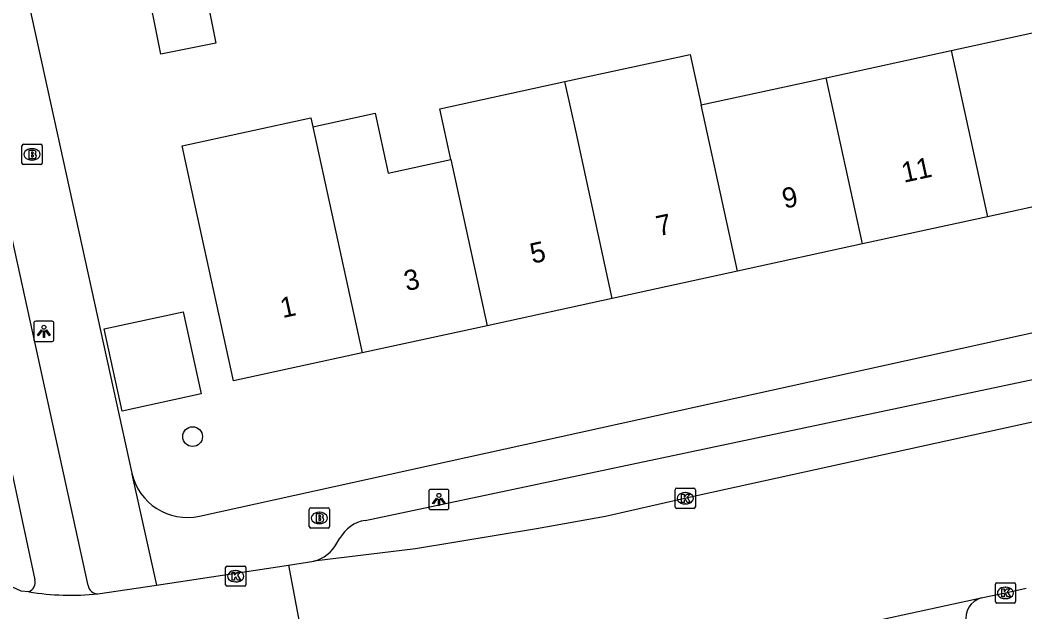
# Model space of a CAD drawing. Extents: x 160557 to 161245, y 385330 to 386505.
# Drawn here: x 160730.97 to 160780.64, y 385909.32 to 385938.59 of the extents above; entities that cross this region are included whole.
import ezdxf

# ---------------------------------------------------------------- set-up
doc = ezdxf.new("R2010")
doc.units = 0
for name, color, linetype in [('IMGEO_Boom', 7, 'Continuous'), ('IMGEO_Brandkraan', 7, 'Continuous'), ('IMGEO_Fietspad_gesloten', 7, 'Continuous'), ('IMGEO_Kolk', 7, 'Continuous'), ('IMGEO_Lichtpunt', 7, 'Continuous'), ('IMGEO_Pand', 7, 'Continuous'), ('IMGEO_Pand_nummerreeks', 7, 'Continuous'), ('IMGEO_Rijbaan_lokaal_gesloten', 7, 'Continuous'), ('IMGEO_Voetpad_open', 7, 'Continuous')]:
    doc.layers.add(name, color=color, linetype=linetype)

msp = doc.modelspace()

# ---------------------------------------------------------------- linework, layer by layer
at = {"layer": 'IMGEO_Boom'}
msp.add_circle((160739.497, 385917.986), 0.489, dxfattribs=at)
at = {"layer": 'IMGEO_Brandkraan'}
for p, q in [((160731.062, 385931.519), (160731.062, 385932.371)), ((160731.137, 385932.445), (160731.989, 385932.445)), ((160732.063, 385932.371), (160732.063, 385931.519)), ((160731.55, 385932.225), (160731.575, 385932.225)), ((160731.989, 385931.445), (160731.137, 385931.445)), ((160731.573, 385931.665), (160731.548, 385931.665)), ((160745.34, 385914.462), (160746.192, 385914.462)), ((160745.265, 385913.536), (160745.265, 385914.388)), ((160745.753, 385914.242), (160745.778, 385914.242)), ((160746.266, 385914.388), (160746.266, 385913.536)), ((160746.192, 385913.462), (160745.34, 385913.462)), ((160745.776, 385913.682), (160745.751, 385913.682))]:
    msp.add_line(p, q, dxfattribs=at)
for points in [[(160731.062, 385931.519), (160731.062, 385932.371)], [(160731.137, 385932.445), (160731.989, 385932.445)], [(160732.063, 385932.371), (160732.063, 385931.519)], [(160731.41, 385932.145), (160731.41, 385931.745), (160731.623, 385931.745)], [(160731.641, 385932.145), (160731.41, 385932.145)], [(160731.589, 385932.064), (160731.535, 385932.064), (160731.535, 385931.988)], [(160731.535, 385931.988), (160731.588, 385931.988)], [(160731.597, 385931.912), (160731.535, 385931.912), (160731.535, 385931.831)], [(160731.535, 385931.831), (160731.597, 385931.831)], [(160731.989, 385931.445), (160731.137, 385931.445)], [(160745.34, 385914.462), (160746.192, 385914.462)], [(160745.265, 385913.536), (160745.265, 385914.388)], [(160745.613, 385914.162), (160745.613, 385913.762), (160745.826, 385913.762)], [(160745.844, 385914.162), (160745.613, 385914.162)], [(160745.792, 385914.081), (160745.738, 385914.081), (160745.738, 385914.005)], [(160745.738, 385914.005), (160745.791, 385914.005)], [(160746.266, 385914.388), (160746.266, 385913.536)], [(160746.192, 385913.462), (160745.34, 385913.462)], [(160745.8, 385913.929), (160745.738, 385913.929), (160745.738, 385913.848)], [(160745.738, 385913.848), (160745.8, 385913.848)]]:
    msp.add_lwpolyline(points, dxfattribs=at)
for centre, radius, start, end in [((160731.139, 385932.369), 0.0765, 91.552, 178.448), ((160731.139, 385932.369), 0.0765, 91.552, 178.448), ((160731.987, 385932.369), 0.0765, 1.552, 88.448), ((160731.987, 385932.369), 0.0765, 1.552, 88.448), ((160731.59, 385932.026), 0.0379, 267.8285, 90.9355), ((160731.598, 385931.871), 0.0404, 269.8759, 90.5077), ((160731.645, 385932), 0.145, 59.4692, 91.5367), ((160731.67, 385932.047), 0.0922, 285.5137, 58.1501), ((160731.675, 385931.855), 0.105, 301.3115, 78.989), ((160731.139, 385931.521), 0.0765, 181.552, 268.448), ((160731.139, 385931.521), 0.0765, 181.552, 268.448), ((160731.629, 385931.996), 0.251, 268.6676, 293.5347), ((160731.987, 385931.521), 0.0765, 271.552, 358.448), ((160731.987, 385931.521), 0.0765, 271.552, 358.448), ((160745.342, 385914.386), 0.0765, 91.552, 178.448), ((160745.342, 385914.386), 0.0765, 91.552, 178.448), ((160746.19, 385914.386), 0.0765, 1.552, 88.448), ((160746.19, 385914.386), 0.0765, 1.552, 88.448), ((160745.793, 385914.043), 0.0379, 267.8285, 90.9355), ((160745.848, 385914.017), 0.145, 59.4692, 91.5367), ((160745.873, 385914.064), 0.0922, 285.5137, 58.1501), ((160745.878, 385913.872), 0.105, 301.3115, 78.989), ((160745.342, 385913.538), 0.0765, 181.552, 268.448), ((160745.342, 385913.538), 0.0765, 181.552, 268.448), ((160745.801, 385913.888), 0.0404, 269.8759, 90.5077), ((160745.832, 385914.013), 0.251, 268.6676, 293.5347), ((160746.19, 385913.538), 0.0765, 271.552, 358.448), ((160746.19, 385913.538), 0.0765, 271.552, 358.448)]:
    msp.add_arc(centre, radius, start, end, dxfattribs=at)
for centre, major_axis, ratio, start_param, end_param in [((160731.549, 385931.945), (-0.387, 0.002), 0.722429, 4.712389, 7.853982), ((160731.574, 385931.945), (-0.39, 0.002), 0.717154, 1.570796, 4.712389), ((160745.752, 385913.962), (-0.387, 0.002), 0.722429, 4.712389, 7.853982), ((160745.777, 385913.962), (-0.39, 0.002), 0.717154, 1.570796, 4.712389)]:
    msp.add_ellipse(centre, major_axis=major_axis, ratio=ratio, start_param=start_param, end_param=end_param, dxfattribs=at)
at = {"layer": 'IMGEO_Fietspad_gesloten'}
for points in [[(160734.335, 385910.619), (160688.379, 386120.515), (160685.475, 386134.246), (160684.879, 386136.929)], [(160730.198, 385917.932), (160731.706, 385910.91)]]:
    msp.add_lwpolyline(points, dxfattribs=at)
for centre, radius, start, end in [((160731.206, 385910.787), 0.515, 292.3979, 13.7854), ((160734.82, 385910.698), 0.492, 189.2151, 270.0695)]:
    msp.add_arc(centre, radius, start, end, dxfattribs=at)
at = {"layer": 'IMGEO_Kolk'}
for p, q in [((160763.425, 385915.435), (160764.277, 385915.435)), ((160763.35, 385914.509), (160763.35, 385915.361)), ((160763.838, 385915.215), (160763.863, 385915.215)), ((160764.351, 385915.361), (160764.351, 385914.509)), ((160764.277, 385914.435), (160763.425, 385914.435)), ((160763.861, 385914.655), (160763.836, 385914.655)), ((160741.129, 385910.656), (160741.129, 385911.508)), ((160741.204, 385911.582), (160742.056, 385911.582)), ((160742.13, 385911.508), (160742.13, 385910.656)), ((160741.617, 385911.362), (160741.642, 385911.362)), ((160742.056, 385910.582), (160741.204, 385910.582)), ((160741.64, 385910.802), (160741.615, 385910.802)), ((160779.176, 385909.83), (160779.176, 385910.682)), ((160779.251, 385910.756), (160780.103, 385910.756)), ((160779.664, 385910.536), (160779.689, 385910.536)), ((160780.177, 385910.682), (160780.177, 385909.83)), ((160779.687, 385909.976), (160779.662, 385909.976)), ((160780.103, 385909.756), (160779.251, 385909.756))]:
    msp.add_line(p, q, dxfattribs=at)
for points in [[(160763.425, 385915.435), (160764.277, 385915.435)], [(160763.35, 385914.509), (160763.35, 385915.361)], [(160763.671, 385915.135), (160763.794, 385915.135), (160763.794, 385914.984), (160763.924, 385915.135), (160764.088, 385915.135), (160763.942, 385914.984), (160764.095, 385914.735), (160763.943, 385914.735), (160763.858, 385914.899), (160763.794, 385914.832), (160763.794, 385914.735), (160763.671, 385914.735), (160763.671, 385915.135)], [(160764.351, 385915.361), (160764.351, 385914.509)], [(160764.277, 385914.435), (160763.425, 385914.435)], [(160741.129, 385910.656), (160741.129, 385911.508)], [(160741.204, 385911.582), (160742.056, 385911.582)], [(160742.13, 385911.508), (160742.13, 385910.656)], [(160741.45, 385911.282), (160741.573, 385911.282), (160741.573, 385911.131), (160741.703, 385911.282), (160741.867, 385911.282), (160741.721, 385911.131), (160741.874, 385910.882), (160741.722, 385910.882), (160741.637, 385911.046), (160741.573, 385910.979), (160741.573, 385910.882), (160741.45, 385910.882), (160741.45, 385911.282)], [(160742.056, 385910.582), (160741.204, 385910.582)], [(160779.176, 385909.83), (160779.176, 385910.682)], [(160779.251, 385910.756), (160780.103, 385910.756)], [(160780.177, 385910.682), (160780.177, 385909.83)], [(160779.497, 385910.456), (160779.62, 385910.456), (160779.62, 385910.305), (160779.75, 385910.456), (160779.914, 385910.456), (160779.768, 385910.305), (160779.921, 385910.056), (160779.769, 385910.056), (160779.684, 385910.22), (160779.62, 385910.153), (160779.62, 385910.056), (160779.497, 385910.056), (160779.497, 385910.456)], [(160780.103, 385909.756), (160779.251, 385909.756)]]:
    msp.add_lwpolyline(points, dxfattribs=at)
for centre, start, end in [((160763.427, 385915.359), 91.552, 178.448), ((160763.427, 385915.359), 91.552, 178.448), ((160764.275, 385915.359), 1.552, 88.448), ((160764.275, 385915.359), 1.552, 88.448), ((160763.427, 385914.511), 181.552, 268.448), ((160763.427, 385914.511), 181.552, 268.448), ((160764.275, 385914.511), 271.552, 358.448), ((160764.275, 385914.511), 271.552, 358.448), ((160741.206, 385911.506), 91.552, 178.448), ((160741.206, 385911.506), 91.552, 178.448), ((160742.054, 385911.506), 1.552, 88.448), ((160742.054, 385911.506), 1.552, 88.448), ((160741.206, 385910.658), 181.552, 268.448), ((160741.206, 385910.658), 181.552, 268.448), ((160742.054, 385910.658), 271.552, 358.448), ((160742.054, 385910.658), 271.552, 358.448), ((160779.253, 385910.68), 91.552, 178.448), ((160779.253, 385910.68), 91.552, 178.448), ((160780.101, 385910.68), 1.552, 88.448), ((160780.101, 385910.68), 1.552, 88.448), ((160779.253, 385909.832), 181.552, 268.448), ((160779.253, 385909.832), 181.552, 268.448), ((160780.101, 385909.832), 271.552, 358.448), ((160780.101, 385909.832), 271.552, 358.448)]:
    msp.add_arc(centre, 0.0765, start, end, dxfattribs=at)
for centre, major_axis, ratio, start_param, end_param in [((160763.837, 385914.935), (-0.387, 0.002), 0.722429, 4.712389, 7.853982), ((160763.862, 385914.935), (-0.39, 0.002), 0.717154, 1.570796, 4.712389), ((160741.616, 385911.082), (-0.387, 0.002), 0.722429, 4.712389, 7.853982), ((160741.641, 385911.082), (-0.39, 0.002), 0.717154, 1.570796, 4.712389), ((160779.663, 385910.256), (-0.387, 0.002), 0.722429, 4.712389, 7.853982), ((160779.688, 385910.256), (-0.39, 0.002), 0.717154, 1.570796, 4.712389)]:
    msp.add_ellipse(centre, major_axis=major_axis, ratio=ratio, start_param=start_param, end_param=end_param, dxfattribs=at)
at = {"layer": 'IMGEO_Lichtpunt'}
for p, q in [((160731.648, 385923.6), (160731.648, 385922.793)), ((160731.648, 385923.6), (160731.648, 385922.793)), ((160732.55, 385923.695), (160731.742, 385923.695)), ((160732.55, 385923.695), (160731.742, 385923.695)), ((160732.644, 385922.793), (160732.644, 385923.6)), ((160732.644, 385922.793), (160732.644, 385923.6)), ((160731.742, 385922.699), (160732.55, 385922.699)), ((160731.742, 385922.699), (160732.55, 385922.699)), ((160751.173, 385915.283), (160751.173, 385914.476)), ((160751.173, 385915.283), (160751.173, 385914.476)), ((160752.075, 385915.378), (160751.267, 385915.378)), ((160752.075, 385915.378), (160751.267, 385915.378)), ((160752.169, 385914.476), (160752.169, 385915.283)), ((160752.169, 385914.476), (160752.169, 385915.283)), ((160751.267, 385914.382), (160752.075, 385914.382)), ((160751.267, 385914.382), (160752.075, 385914.382))]:
    msp.add_line(p, q, dxfattribs=at)
for points in [[(160732.022, 385923.264), (160732.061, 385923.236), (160731.873, 385922.974), (160731.835, 385923.001), (160732.022, 385923.264)], [(160732.124, 385923.216), (160732.171, 385923.216), (160732.171, 385922.894), (160732.124, 385922.894), (160732.124, 385923.216)], [(160732.234, 385923.236), (160732.272, 385923.263), (160732.459, 385923.001), (160732.42, 385922.973), (160732.234, 385923.236)], [(160751.547, 385914.947), (160751.586, 385914.919), (160751.398, 385914.657), (160751.36, 385914.684), (160751.547, 385914.947)], [(160751.759, 385914.919), (160751.797, 385914.946), (160751.984, 385914.684), (160751.945, 385914.656), (160751.759, 385914.919)], [(160751.649, 385914.899), (160751.696, 385914.899), (160751.696, 385914.577), (160751.649, 385914.577), (160751.649, 385914.899)]]:
    msp.add_lwpolyline(points, dxfattribs=at)
for centre in [(160732.147, 385923.398), (160751.672, 385915.081)]:
    msp.add_circle(centre, 0.0994, dxfattribs=at)
for centre, start, end in [((160731.742, 385923.6), 90, 180), ((160731.742, 385923.6), 90, 180), ((160732.55, 385923.6), 0, 90), ((160732.55, 385923.6), 0, 90), ((160731.742, 385922.793), 180, 270), ((160731.742, 385922.793), 180, 270), ((160732.55, 385922.793), 270, 0), ((160732.55, 385922.793), 270, 360), ((160751.267, 385915.283), 90, 180), ((160751.267, 385915.283), 90, 180), ((160752.075, 385915.283), 0, 90), ((160752.075, 385915.283), 0, 90), ((160751.267, 385914.476), 180, 270), ((160751.267, 385914.476), 180, 270), ((160752.075, 385914.476), 270, 0), ((160752.075, 385914.476), 270, 360)]:
    msp.add_arc(centre, 0.0946, start, end, dxfattribs=at)
at = {"layer": 'IMGEO_Pand'}
for points in [[(160739.868, 385941.328), (160740.651, 385937.453), (160737.93, 385936.903), (160737.146, 385940.778)], [(160776.999, 385937.087), (160783.35, 385938.471), (160783.85, 385936.177), (160784.078, 385935.132), (160785.143, 385930.246), (160778.791, 385928.861)], [(160757.905, 385935.545), (160764.087, 385936.892), (160764.632, 385934.391)], [(160770.816, 385935.739), (160776.999, 385937.087)], [(160776.999, 385937.087), (160778.791, 385928.861)], [(160752.267, 385931.695), (160751.722, 385934.198), (160757.905, 385935.545)], [(160760.243, 385924.818), (160758.45, 385933.043), (160757.905, 385935.545)], [(160764.632, 385934.391), (160770.816, 385935.739)], [(160772.608, 385927.514), (160770.816, 385935.739)], [(160766.424, 385926.166), (160764.632, 385934.391)], [(160745.439, 385933.314), (160748.515, 385933.984), (160749.161, 385931.018), (160752.267, 385931.695)], [(160747.877, 385922.123), (160741.525, 385920.738), (160739.732, 385928.963), (160738.991, 385932.365), (160745.342, 385933.75), (160745.439, 385933.314)], [(160745.439, 385933.314), (160747.877, 385922.123)], [(160752.267, 385931.695), (160754.059, 385923.47)], [(160778.791, 385928.861), (160772.608, 385927.514)], [(160772.608, 385927.514), (160766.424, 385926.166)], [(160766.424, 385926.166), (160760.243, 385924.818)], [(160760.243, 385924.818), (160754.059, 385923.47)], [(160739.03, 385924.166), (160739.917, 385920.096), (160736.015, 385919.246), (160735.128, 385923.315), (160739.03, 385924.166)], [(160754.059, 385923.47), (160747.877, 385922.123)]]:
    msp.add_lwpolyline(points, dxfattribs=at)
at = {"layer": 'IMGEO_Rijbaan_lokaal_gesloten'}
for points in [[(160840.924, 385932.085), (160816.018, 385926.352), (160787.915, 385920.21), (160763.809, 385914.925), (160759.912, 385914.039), (160756.492, 385913.428), (160750.518, 385912.437), (160745.49, 385911.828)], [(160737.71, 385910.645), (160744.233, 385911.636)], [(160744.233, 385911.636), (160745.49, 385911.828)], [(160744.233, 385911.636), (160746.075, 385901.918)], [(160731.402, 385910.311), (160731.032, 385910.335), (160728.768, 385911.384)], [(160734.821, 385910.206), (160737.71, 385910.645)], [(160778.483, 385910.006), (160779.677, 385910.257), (160780.7, 385910.486)], [(160770.117, 385908.203), (160778.483, 385910.006)]]:
    msp.add_lwpolyline(points, dxfattribs=at)
msp.add_arc((160733.52, 385923.547), 13.405, 260.9107, 275.5713, dxfattribs=at)
at = {"layer": 'IMGEO_Voetpad_open'}
for points in [[(160731.429, 385939.532), (160731.466, 385939.363), (160731.404, 385939.381), (160736.496, 385916.182)], [(160739.836, 385914.053), (160789.869, 385925.075)], [(160748.031, 385913.844), (160786.716, 385922.012)], [(160736.496, 385916.182), (160736.503, 385916.132), (160737.71, 385910.645)], [(160746.633, 385912.71), (160746.776, 385912.961)]]:
    msp.add_lwpolyline(points, dxfattribs=at)
for centre, radius, start, end in [((160739.231, 385916.788), 2.801, 192.4935, 282.4775), ((160748.325, 385912.093), 1.775, 99.5213, 150.738), ((160745.041, 385913.591), 1.82, 284.282, 331.0294), ((160778.745, 385909.015), 1.025, 104.8202, 192.6302)]:
    msp.add_arc(centre, radius, start, end, dxfattribs=at)

# ---------------------------------------------------------------- texts
at = {"layer": 'IMGEO_Pand_nummerreeks'}
for s, rotation, p in [('11', 12.2972, (160774.653, 385930.539)), ('9', 12.2972, (160768.759, 385929.254)), ('7', 12.2972, (160762.528, 385927.895)), ('5', 12.2957, (160756.297, 385926.536)), ('3', 12.2972, (160750.066, 385925.179)), ('1', 12.2972, (160743.946, 385923.845))]:
    msp.add_text(s, height=1, rotation=rotation, dxfattribs=at).set_placement(p)

doc.saveas('drawing.dxf')
